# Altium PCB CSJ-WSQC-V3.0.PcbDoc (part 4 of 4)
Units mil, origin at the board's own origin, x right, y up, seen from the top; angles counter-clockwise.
Board outline 5060 x 7131.55 mil, 4 copper layers (Top Layer, InternalPlane1, InternalPlane2, Bottom Layer); 390 components, 277 nets, 1183 pads, 601 vias.
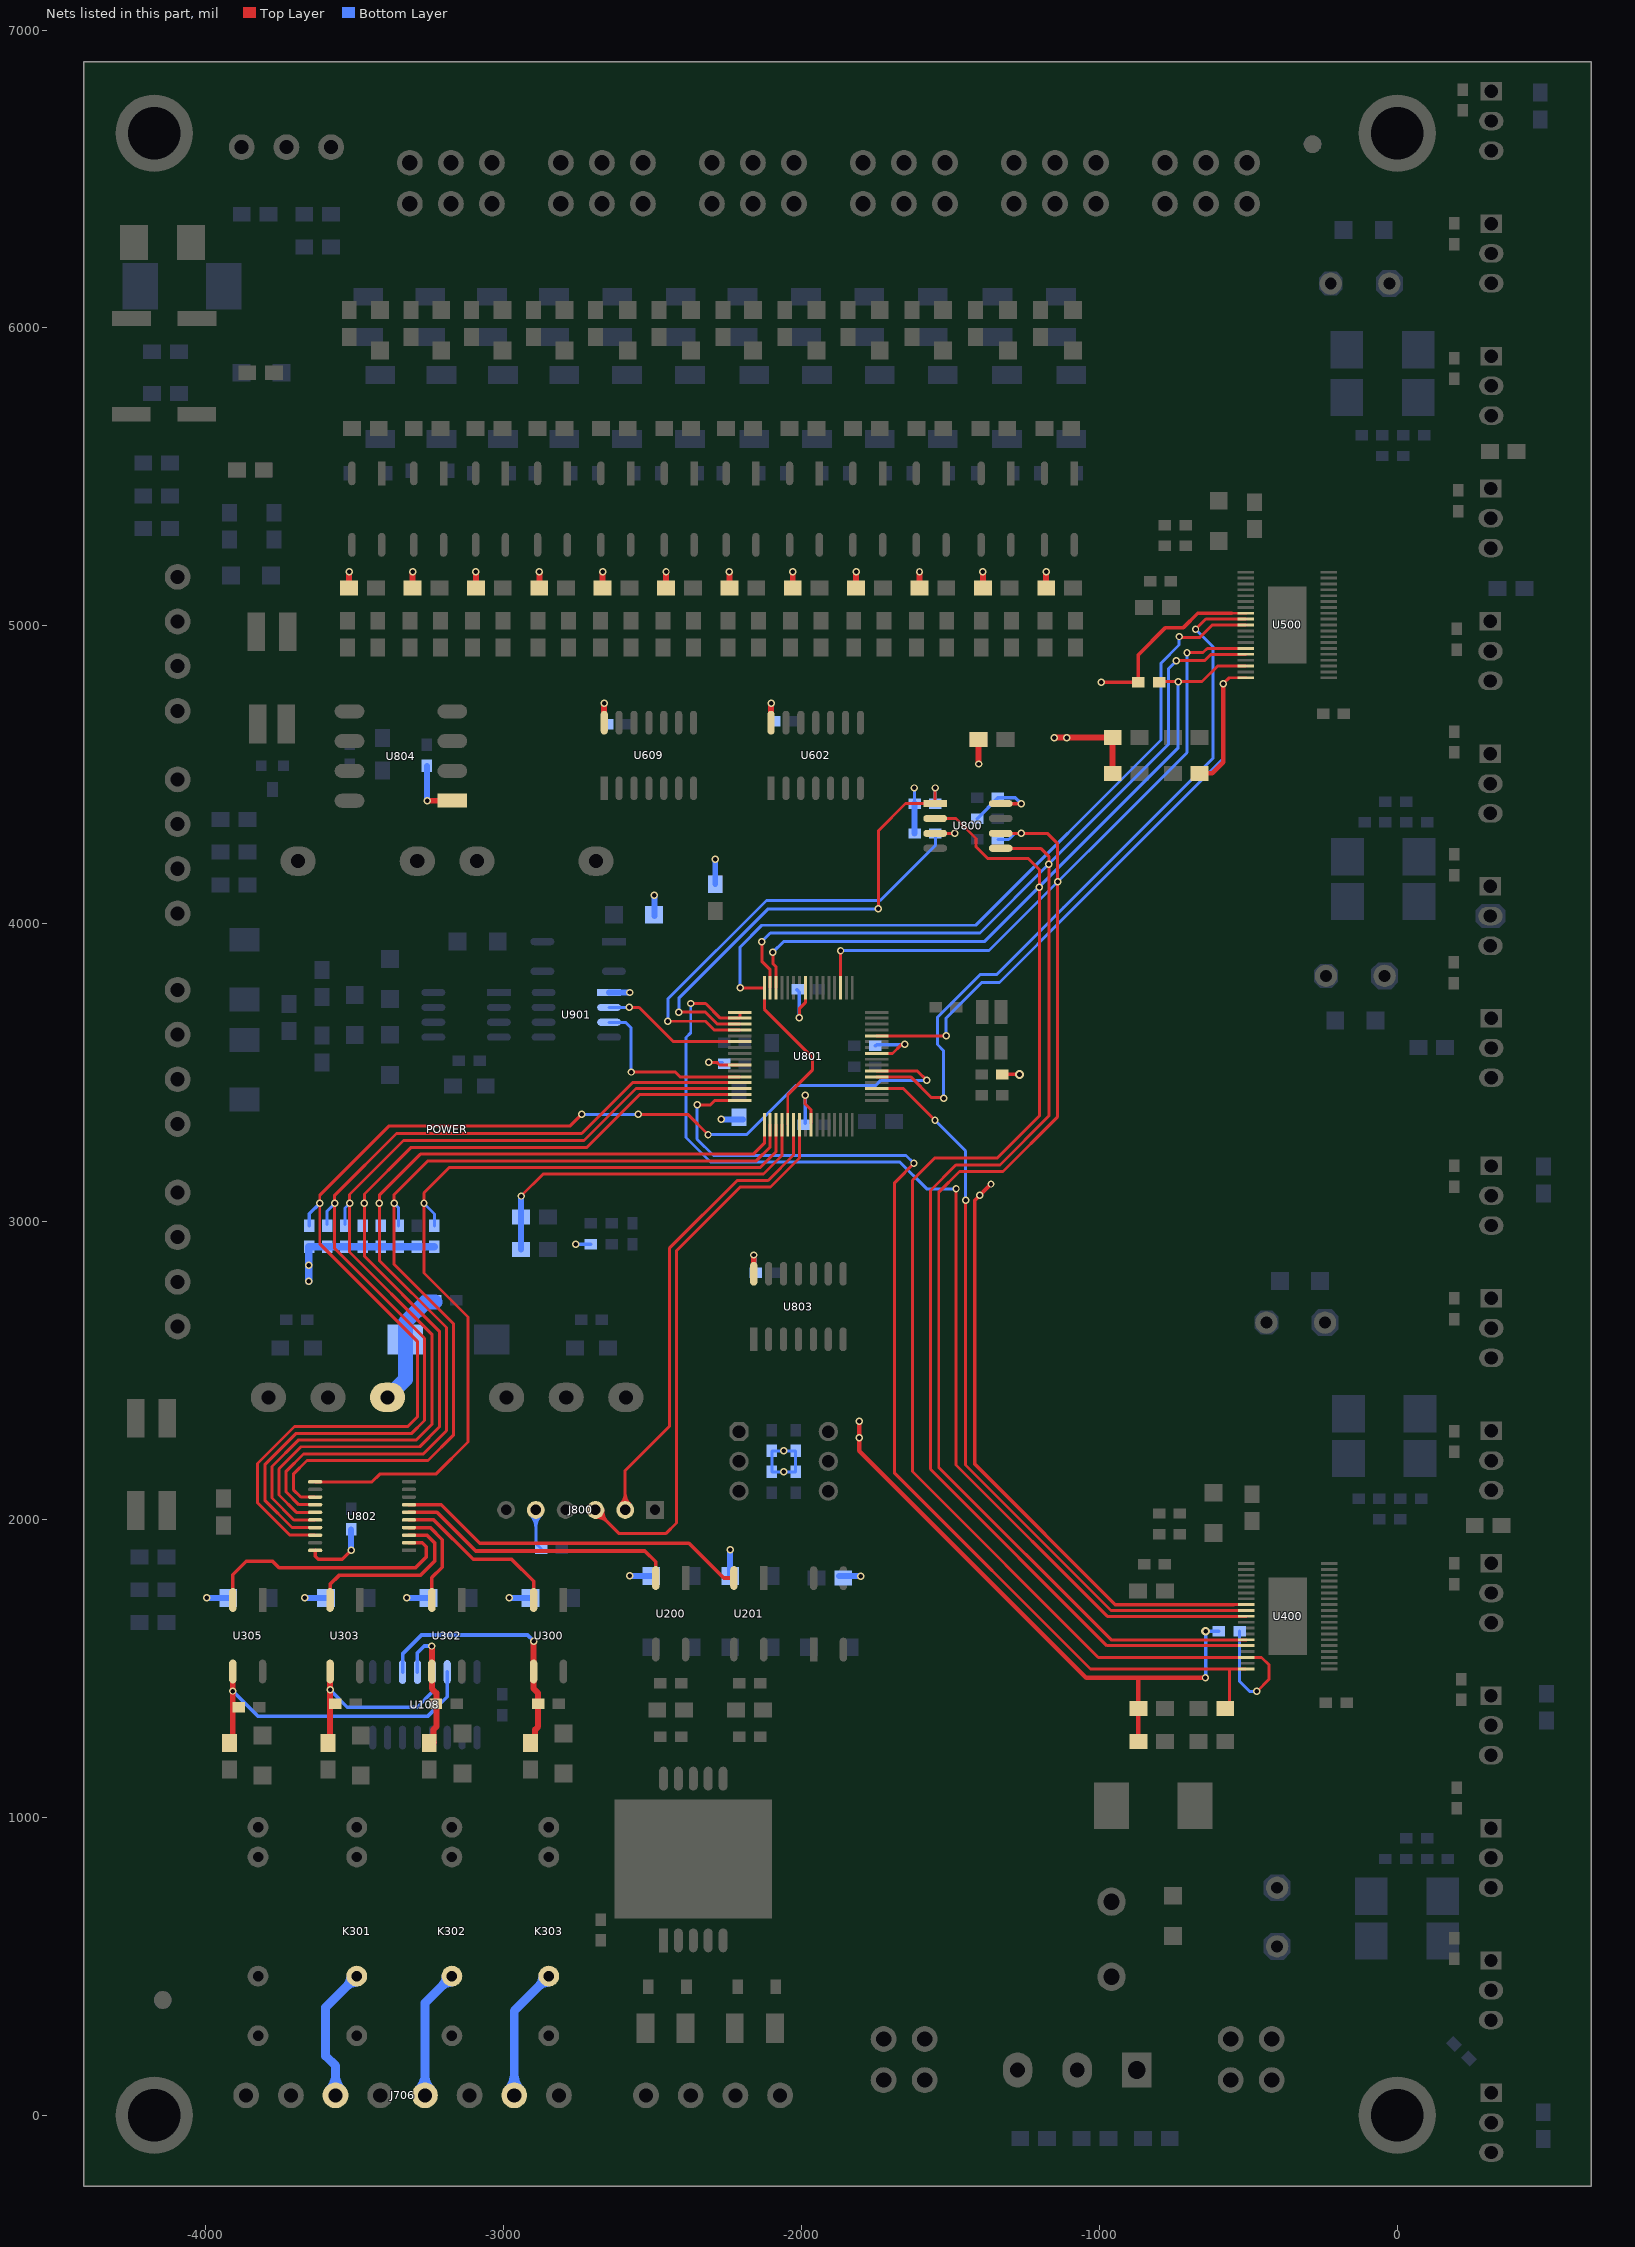
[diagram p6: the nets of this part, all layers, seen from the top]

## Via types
v1: diameter 25, hole 15, Top Layer to Bottom Layer, 303 vias
v2: diameter 25, hole 12, Top Layer to Bottom Layer, 94 vias
v3: diameter 50, hole 25, Top Layer to Bottom Layer, 71 vias
v4: diameter 30, hole 16, Top Layer to Bottom Layer, 71 vias
v5: diameter 12, hole 8, Top Layer to Bottom Layer, 25 vias
v6: diameter 25, hole 12, Top Layer to Bottom Layer, tented both sides, 24 vias
v7: diameter 35, hole 20, Top Layer to Bottom Layer, 7 vias
v8: diameter 20, hole 12, Top Layer to Bottom Layer, 3 vias
v9: diameter 8, hole 5, Top Layer to Bottom Layer, 2 vias
v10: diameter 35, hole 25, Top Layer to Bottom Layer, 1 vias

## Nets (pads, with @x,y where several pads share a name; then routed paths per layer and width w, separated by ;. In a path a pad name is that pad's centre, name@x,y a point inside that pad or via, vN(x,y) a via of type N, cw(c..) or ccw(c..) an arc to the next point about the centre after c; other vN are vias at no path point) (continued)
OUT6: J706.3 K301.2 | length 708.4
  Bottom Layer w30: J706.3@-3584.46,86.75 ccw(c-3632.79,135.07) -3564.45,135.07 ccw(c-3496.11,135.07) J706.3@-3544.43,86.75 ; J706.3@-3564.45,66.73 -3564.45,165.73 -3597.45,198.73 -3597.45,362.4 K301.2@-3493.11,466.73 ; K301.2@-3513.11,466.73 cw(c-3561.4,466.73) -3527.26,432.59 ; -3527.26,432.59 cw(c-3493.11,398.45) -3493.11,446.73 K301.2@-3493.11,466.73 ; -3527.26,432.59 K301.2@-3493.11,466.73
OUT7: J706.5 K302.2 | length 689
  Bottom Layer w30: J706.5@-3284.46,86.75 ccw(c-3332.79,135.07) -3264.45,135.07 ccw(c-3196.11,135.07) J706.5@-3244.43,86.75 ; J706.5@-3264.45,66.73 -3264.45,174 -3264.45,376.07 K302.2@-3173.78,466.73 ; K302.2@-3193.78,466.73 cw(c-3242.07,466.73) -3207.92,432.59 ; -3207.92,432.59 cw(c-3173.78,398.45) -3173.78,446.73 K302.2@-3173.78,466.73 ; -3207.92,432.59 K302.2@-3173.78,466.73
OUT8: J706.7 K303.2 | length 699.5
  Bottom Layer w30: J706.7@-2984.46,86.75 ccw(c-3032.79,135.07) -2964.45,135.07 ccw(c-2896.11,135.07) J706.7@-2944.43,86.75 ; J706.7@-2964.45,66.73 -2964.45,350.73 K303.2@-2848.45,466.73 ; K303.2@-2868.45,466.73 cw(c-2916.73,466.73) -2882.59,432.59 ; -2882.59,432.59 cw(c-2848.45,398.45) -2848.45,446.73 K303.2@-2848.45,466.73 ; -2882.59,432.59 K303.2@-2848.45,466.73
"OUT ALARM_IN1": C205.2 R222.2 U801.20 | length 1215.2
  Top Layer w10: v1(-2941.45,3085.73) -2867.18,3160 -2128,3160 -2066.03,3221.97 U801.20@-2066.03,3325.32
  Bottom Layer w20: R222.2@-2941.45,2905.73 C205.2@-2941.45,3015.73 v1(-2941.45,3085.73)
PGC: J800.2 U801.22 | length 1733.4
  Top Layer w10: J800.2@-2608.69,2050.61 ccw(c-2642.21,2088) -2592,2088 ; J800.2@-2602.01,2043.17 ccw(c-2622.13,2065.6) -2592,2065.6 ccw(c-2561.87,2065.6) J800.2@-2581.99,2043.17 ; J800.2@-2592,2032 -2592,2088 ; -2592,2098 -2592,2088 ; J800.2@-2575.31,2050.61 cw(c-2541.79,2088) -2592,2088 ; U801.22@-2026.66,3325.32 -2026.66,3223.34 -2112,3138 -2216,3138 -2444,2910 -2444,2312 -2592,2164 -2592,2088
PGD: J800.3 U801.23 | length 2039.9
  Top Layer w10: J800.3@-2692,2007 cw(c-2692,1946.65) -2649.32,1989.32 cw(c-2606.64,2032) J800.3@-2667,2032 ; J800.3@-2692,2017 cw(c-2692,1980.79) -2666.39,2006.39 cw(c-2640.79,2032) J800.3@-2677,2032 ; J800.3@-2692,2032 -2612,1952 -2456,1952 -2420,1988 -2420,2902 -2206,3116 -2104,3116 -2006.98,3213.02 U801.23@-2006.98,3325.32
PO5: C300.2 R304.2 U108.3 U300.3 | length 885.9
  Top Layer w20: v1(-2899.45,1591.73) U300.3@-2899.45,1489.53 -2899.45,1431.73 -2884.45,1416.73 C300.2@-2884.45,1381.73 -2884.45,1304.53 -2894.45,1294.53 R304.2@-2894.45,1251.73
  Bottom Layer w12: U108.3@-3339.45,1487.73 -3339.45,1548.55 -3276,1612 -2919.72,1612 v1(-2899.45,1591.73)
PO6: C302.2 R309.2 U108.4 U302.3 | length 457.8
  Top Layer w20: v1(-3241.11,1575.07) U302.3@-3241.11,1489.53 -3241.11,1431.73 -3226.11,1416.73 -3226.11,1304.53 -3236.11,1294.53 -3236.11,1251.73 R309.2@-3234.45,1251.73
  Bottom Layer w12: U108.4@-3289.45,1487.73 -3289.45,1552.55 -3266.93,1575.07 v1(-3241.11,1575.07)
PO7: C303.2 R318.2 U108.5 U303.3 | length 696
  Top Layer w20: R318.2@-3590,1250 -3582.78,1257.22 v1(-3582.78,1428) U303.3@-3582.78,1489.53
  Bottom Layer w12: v1@-3578,1428 -3578,1423.22 -3524.78,1370 -3290,1370 -3239.45,1420.55 U108.5@-3239.45,1487.73
PO8: C305.2 R323.2 U108.6 U305.3 | length 1102.5
  Top Layer w20: R323.2@-3909.45,1260.55 v1(-3909.45,1424) U305.3@-3909.45,1489.53 ; R323.2@-3904.45,1251.73 R323.2@-3904.45,1260.55
  Bottom Layer w12: v1(-3909.45,1424) -3825.45,1340 -3254,1340 -3189.45,1404.55 U108.6@-3189.45,1487.73
PRE485_EN: R819.1 U801.19 U802.11 | length 2885.3
  Top Layer w10: U802.11@-3632.96,2126.31 -3441.69,2126.31 -3416,2152 -3228,2152 -3120,2260 -3120,2680 -3267.45,2827.45 v1(-3267.45,3060.73) -3267.45,3096.55 -3182,3182 -2138,3182 -2085.72,3234.28 U801.19@-2085.72,3325.32
  Bottom Layer w10: v1(-3267.45,3060.73) -3232.45,3025.73 R819.1@-3232.45,2985.73
"PRE 1": R816.1 U801.17 U802.14 | length 3260.2
  Top Layer w10: U802.14@-3632.96,2049.54 -3687.54,2049.54 -3730,2092 -3730,2162 -3672,2220 -3270,2220 -3192,2298 -3192,2644 -3417.45,2869.45 v1(-3417.45,3060.73) ; -3417.45,2965.45 v1(-3417.45,3060.73) ; U801.17@-2125.09,3325.32 -2125.09,3262.91 -2162,3226 -3280,3226 -3417.45,3088.55 v1(-3417.45,3060.73)
  Bottom Layer w10: R816.1@-3417.45,2985.73 v1(-3417.45,3060.73)
"PRE 2": R817.1 U801.18 U802.13 | length 3166
  Top Layer w10: U802.13@-3632.96,2075.13 -3681.13,2075.13 -3706,2100 -3706,2152 -3660,2198 -3254,2198 -3168,2284 -3168,2656 -3367.45,2855.45 -3367.45,3034 ; -3367.45,2969.45 -3367.45,3034 ; U801.18@-2105.4,3325.32 -2105.4,3250.6 -2152,3204 -3254,3204 -3367.45,3090.55 v1(-3367.45,3060.73) -3367.45,3034
  Bottom Layer w10: v1(-3367.45,3060.73) -3352.45,3045.73 R817.1@-3352.45,2985.73
"PRE 5": R815.1 U801.15 U802.15 | length 3216
  Top Layer w10: U802.15@-3632.96,2023.95 -3695.95,2023.95 -3754,2082 -3754,2170 -3680,2244 -3282,2244 -3216,2310 -3216,2632 -3467.45,2883.45 v1(-3467.45,3060.73) -3467.45,3092.55 -3312,3248 -2722,3248 -2543.22,3426.78 -2406,3426.78 ; -2427.22,3426.78 -2406,3426.78 ; U801.15@-2206.86,3426.78 -2406,3426.78
  Bottom Layer w10: R815.1@-3467.45,2980.73 v1(-3467.45,3060.73)
"PRE 6": R814.1 U801.14 U802.16 | length 3347.6
  Top Layer w10: U802.16@-3632.96,1998.36 -3704.36,1998.36 -3778,2072 -3778,2178 -3690,2266 -3294,2266 -3240,2320 -3240,2620 -3517.45,2897.45 v1(-3517.45,3060.73) -3517.45,3090.55 -3336,3272 -2730,3272 -2555.53,3446.47 -2390,3446.47 ; -2439.53,3446.47 -2390,3446.47 ; U801.14@-2206.86,3446.47 -2390,3446.47
  Bottom Layer w10: R814.1@-3532.45,2990.73 -3532.45,3045.73 v1(-3517.45,3060.73)
"PRE 7": R812.1 U801.13 U802.17 | length 3420.7
  Top Layer w10: U802.17@-3632.96,1972.77 -3710.77,1972.77 -3802,2064 -3802,2184 -3698,2288 -3310,2288 -3266,2332 -3266,2608 -3567.45,2909.45 v1(-3567.45,3060.73) -3567.45,3088.55 -3360,3296 -2738,3296 -2567.85,3466.15 -2434,3466.15 ; -2451.85,3466.15 -2434,3466.15 ; U801.13@-2206.86,3466.15 -2434,3466.15
  Bottom Layer w10: R812.1@-3592.45,2990.73 -3592.45,3035.73 v1(-3567.45,3060.73)
"PRE 8": R811.1 U801.38 U802.18 | length 4374.9
  Top Layer w10: U802.18@-3632.96,1947.18 -3717.18,1947.18 -3826,2056 -3826,2188 -3702,2312 -3322,2312 -3290,2344 -3290,2598 -3617.45,2925.45 v1(-3617.45,3060.73) -3617.45,3088.55 -3386,3320 -2778,3320 v1(-2738,3360) ; v1(-2548,3360) -2382,3360 v1(-2314,3292) ; U801.38@-1748.04,3505.52 -1611.52,3505.52 v1(-1580,3474)
  Bottom Layer w10: v1(-2738,3360) v1(-2548,3360) ; v1(-2314,3292) -2184,3292 -2020,3456 -1752,3456 -1734,3474 v1(-1580,3474)
  Bottom Layer w12: R811.1@-3652.45,2985.73 -3652.45,3025.73 v1(-3617.45,3060.73)
"PRE OUT1": U200.2 U802.6 | length 951.4
  Top Layer w12: U802.6@-3318,2023.95 -3223.95,2023.95 -3094,1894 -2526,1894 -2489.45,1857.45 U200.2@-2489.45,1803.53
"PRE OUT2": U201.2 U802.7 | length 1193
  Top Layer w12: U802.7@-3318,2049.54 -3209.54,2049.54 -3080,1920 -2378,1920 -2261.53,1803.53 U201.2@-2226.95,1803.53
"PRE OUT5": U300.2 U802.5 | length 566.5
  Top Layer w12: U802.5@-3318,1998.36 -3234.36,1998.36 -3102,1866 -2973.45,1866 -2899.45,1792 U300.2@-2899.45,1729.53
"PRE OUT6": U302.2 U802.4 | length 345.9
  Top Layer w12: U802.4@-3318,1972.77 -3246.77,1972.77 -3206,1932 -3206,1840 -3241.11,1804.89 U302.2@-3241.11,1729.53
"PRE OUT7": U303.2 U802.3 | length 594
  Top Layer w12: U303.2@-3582.78,1729.53 -3582.78,1782 -3552.78,1812 -3280,1812 -3232,1860 -3232,1922 -3257.18,1947.18 U802.3@-3318,1947.18
"PRE OUT8": U305.2 U802.2 | length 875
  Top Layer w12: U305.2@-3909.45,1729.53 -3909.45,1814.55 -3864,1860 -3776,1860 -3754,1838 -3296,1838 -3260,1874 -3260,1908 -3273.59,1921.59 U802.2@-3318,1921.59
PROTECTION: R807.2 U800.3 U801.4 | length 1610.8
  Top Layer w10: v1(-2448.83,3672.47) -2322.47,3672.47 -2293.32,3643.32 U801.4@-2206.86,3643.32 ; U800.3@-1551.45,4303.17 v1(-1485.06,4303.17)
  Bottom Layer w10: v1@-2448.83,3674.73 -2448.83,3747.17 -2118,4078 -1736,4078 -1550.62,4263.38 R807.2@-1550.62,4302.73 ; R807.2@-1551.45,4302.73 R807.2@-1550.62,4302.73 ; v1(-1485.06,4303.17) -1550.18,4303.17 R807.2@-1550.62,4302.73
RES1: U400.9 U801.35 | length 2583
  Top Layer w10: U801.35@-1748.04,3446.47 -1658.47,3446.47 v1(-1552,3340) ; v1@-1449.45,3074 v1(-1449.45,3072) -1449.45,2182.73 -961.13,1694.42 U400.9@-506.62,1694.42
  Bottom Layer w10: v1(-1552,3340) -1449.45,3237.45 v1@-1449.45,3076
RES2: U500.9 U801.37 | length 2463.5
  Top Layer w10: U801.37@-1748.04,3485.84 -1633.84,3485.84 -1564,3416 v1@-1524,3416 ; v1(-677.45,4988) -643.03,5022.42 U500.9@-508.62,5022.42
  Bottom Layer w10: v1@-1524,3414 -1524,3574 -1544,3594 -1544,3686 -1401.27,3828.73 -1345.45,3828.73 -1118.09,4056.09 ; -1121.09,4053.09 -1118.09,4056.09 ; v1(-677.45,4988) -618,4928.55 -618,4556.18 -1118.09,4056.09
  other v1: -1522,3414
RS485RXD: U801.6 U901.2 | length 486.8
  Top Layer w10: v1(-2579,3719) -2545,3719 -2429.95,3603.95 U801.6@-2206.86,3603.95
  Bottom Layer w10: U901.2@-2646,3719 v1(-2579,3719)
RS485TXD: U801.12 U901.3 | length 601.7
  Top Layer w10: v1(-2572,3502) -2424,3502 -2407.84,3485.84 U801.12@-2206.86,3485.84
  Bottom Layer w10: U901.3@-2646,3669 -2591,3669 -2572,3650 v1(-2572,3502)
SPICLK: R808.1 U400.14 U500.14 U800.6 U801.51 | length 6012.5
  Top Layer w10: U801.51@-1869.18,3784.14 v1(-1869.18,3909.73) ; U800.6@-1331.45,4303.17 v1(-1262.18,4303.17) -1175.17,4303.17 -1140,4268 -1140,4238 v1(-1140,4140) ; v1@-1139.72,4139.72 -1140,4139.43 -1140,3352 -1324,3168 -1470,3168 -1539.45,3098.55 -1539.45,2174.73 -960.71,1595.99 U400.14@-506.62,1595.99 ; v1(-706,4910) -652,4910 -638.01,4923.99 U500.14@-508.62,4923.99
  Bottom Layer w10: v1(-1869.18,3909.73) -1370.45,3909.73 -706,4574.18 v1(-706,4910) ; R808.1@-1340.62,4282.73 -1304.62,4282.73 -1284.18,4303.17 v1(-1262.18,4303.17)
SPISIMO: U400.15 U500.15 U800.5 U801.63 | length 6127.6
  Top Layer w10: v1(-2133.45,3940) -2133.45,3873.45 -2105.4,3845.4 U801.63@-2105.4,3784.14 ; U800.5@-1331.45,4253.17 -1197.17,4253.17 -1170,4226 -1170,4204 v1(-1170,4200) -1170,3354 -1334,3190 -1482,3190 -1567.45,3104.55 -1567.45,2168.73 -975.02,1576.31 U400.15@-506.62,1576.31 ; v1@-742,4882.73 v1@-741.79,4882.73 ; v1@-741.79,4882.94 -647.06,4882.94 -625.69,4904.31 U500.15@-508.62,4904.31
  Bottom Layer w10: v1(-2133.45,3940) -2104.72,3968.73 -1401.27,3968.73 v1(-1170,4200) -768,4602 -768,4856 v1(-742,4882)
SPISOMI: R406.2 R506.2 U400.17 U500.17 U800.2 U801.62 | length 6895.4
  Top Layer w10: v1(-2096.62,3904) -2096.62,3866.62 -2085.72,3855.72 U801.62@-2085.72,3784.14 ; U800.2@-1551.45,4353.17 -1481.17,4353.17 -1414,4286 -1414,4258 -1374,4218 -1238,4218 -1202,4182 v1(-1202,4122) -1202,3790 ; -1202,3812 -1202,3790 ; R506.2@-800,4812.73 v1(-735.45,4812.73) -655.27,4812.73 -603.06,4864.94 U500.17@-508.62,4864.94 ; v1(-471.45,1422.73) -431.45,1462.73 -431.45,1512.73 -455.65,1536.94 U400.17@-506.62,1536.94 -1003.65,1536.94 -1627.45,2160.73 -1627.45,3138.55 -1552,3214 -1342,3214 -1202,3354 -1202,3790
  Bottom Layer w10: v1(-2096.62,3904) -2060.89,3939.73 -1386.27,3939.73 -735.45,4590.55 v1(-735.45,4812.73) ; R406.2@-529.45,1624.73 -529.45,1456.77 -495.41,1422.73 v1(-471.45,1422.73)
SPISTE: R802.2 U800.1 U801.3 | length 1659.5
  Top Layer w10: v1(-2412,3702.73) -2322.73,3702.73 -2283,3663 U801.3@-2206.86,3663 ; v1@-1741.45,4050.55 v1(-1742,4050) -1742,4312.18 -1651.01,4403.17 U800.1@-1551.45,4403.17 v1(-1551.45,4455.56)
  Bottom Layer w10: v1@-2408,3704.73 -2412,3708.73 -2412,3750 -2112,4050 v1(-1742,4050) ; v1(-1551.45,4455.56) -1551.45,4403.56 R802.2@-1550.62,4402.73
STALLN_1: R410.1 U400.19 U801.16 | length 3694.3
  Top Layer w10: v1(-2350,3392) -2306,3392 -2290.91,3407.09 U801.16@-2206.86,3407.09 ; v1@-1618,3200 -1687.45,3130.55 -1687.45,2154.73 -1030.28,1497.57 -563.45,1497.57 ; R410.1@-589.45,1364.73 -563.45,1390.73 -563.45,1497.57 ; U400.19@-509.45,1497.57 -563.45,1497.57
  Bottom Layer w10: v1@-2350.62,3392 -2350.62,3276.62 -2296,3222 -1649.17,3222 v1(-1622.59,3195.41)
STALLN_2: R510.1 U500.19 U801.44 | length 2297.9
  Top Layer w10: U801.44@-1748.04,3623.63 v1(-1514.37,3623.63) v1@-1514,3624 ; v1(-584,4806) -564.43,4825.57 U500.19@-508.62,4825.57
  Top Layer w15: R510.1@-675.45,4504.73 R510.1@-663.45,4504.73 -621.27,4504.73 -584,4542 v1(-584,4806)
  Bottom Layer w10: v1@-1514.37,3622.73 -1514.37,3683.63 -1395.27,3802.73 -1335.45,3802.73 -1080.09,4058.09 ; -1084.09,4054.09 -1080.09,4058.09 ; v1(-584,4806) -584,4554.18 -1080.09,4058.09
STEP_1: U400.10 U801.1 U801.2 | length 3752.2
  Top Layer w10: v1(-2372,3732) -2322,3732 -2272.69,3682.69 U801.2@-2206.86,3682.69 U801.1@-2206.86,3702.37 ; v1(-1481.45,3110) -1481.45,2182.73 -973.45,1674.73 U400.10@-506.62,1674.73
  Bottom Layer w10: v1(-2372,3732) -2372,3634 -2388,3618 -2388,3282 -2306,3200 -1670,3200 -1580,3110 v1(-1481.45,3110)
STEP_2: U500.10 U801.21 U801.64 | length 3091.3
  Top Layer w10: v1(-2206,3784.73) U801.64@-2125.68,3784.73 ; U801.64@-2125.09,3784.14 -2125.09,3713.09 -1964,3552 -1964,3508 -2046.35,3425.65 U801.21@-2046.35,3325.32 ; v1@-732,4960 -664,4960 -621.27,5002.73 U500.10@-508.62,5002.73
  Bottom Layer w10: v1(-2206,3784.73) -2206,3922 -2133.27,3994.73 -1415.27,3994.73 -793.45,4616.55 -793.45,4874.55 -732.5,4935.5 v1@-732.5,4964
  other v1: -732,4964
VCC: C110.1 C111.1 C612.1 C613.1 C800.2 C802.1 C807.1 C809.1 C810.1 C811.1 C812.1 C817.1 C818.1 D102.1 D400.1 D401.1 D500.1 D501.1 J800.5 L100.1 L800.1 POWER.8 R201.2 R205.2 R220.1 R301.2 R306.2 R315.2 R320.2 R406.1 R506.1 R600.2 R601.2 R610.2 R611.2 R620.2 R621.2 R630.2 R631.2 R640.2 R641.2 R650.2 R651.2 R800.2 R801.1 R802.1 R803.2 R804.1 R805.1 R806.2 R807.1 R810.2 R811.2 R812.2 R814.2 R815.2 R816.2 R817.2 R818.2 R819.2 R904.2 U400.8 U500.8 U602.14 U609.14 U800.8 U801.10 U801.25 U801.41 U801.57 U802.20 U803.14 U804.1 U901.1 | length 10160.7
  Top Layer w10: v1(-2312,3534.73) -2284.62,3534.73 -2275.09,3525.21 U801.10@-2206.86,3525.21 ; v1(-2007.45,3684.73) -2007.45,3714.73 -1987.29,3734.89 U801.57@-1987.29,3779.14 ; v1(-1987.76,3424.73) -1987.76,3394.73 -1967.61,3374.58 U801.25@-1967.61,3330.32 ; U801.41@-1723.04,3564.58 -1694.78,3564.58 -1665.53,3593.82 v1@-1648.53,3593.82 ; L800.1@-1325.45,3493.73 L800.1@-1325.18,3493.73 ; -556,5042.1 U500.8@-508.62,5042.1 ; -550,1714.1 U400.8@-506.62,1714.1
  Top Layer w12: U802.20@-3632.05,1895.09 U802.20@-3632.96,1896 -3632.96,1876.96 -3622,1866 -3542,1866 v1@-3512.91,1895.09 ; v1(-1364,3126) -1418,3072 -1418,2185.28 -946.82,1714.1 -550,1714.1 ; U800.8@-1331.45,4403.17 v1(-1263.06,4403.17) ; L800.1@-1325.18,3494 v4(-1268,3494) ; v1(-994,4810) R506.1@-870,4810 -870,4902 -778,4994 -718,4994 -669.9,5042.1 -556,5042.1
  Top Layer w15: v1(-1806,2330) -1806,2230 -1044,1468 -869.45,1468 ; D401.1@-869.45,1254.73 D400.1@-869.45,1364.73 -869.45,1468 ; v1@-640,1468 -869.45,1468
  Top Layer w20: R651.2@-3518.62,5126.73 v1(-3518.62,5181.73) ; R641.2@-3305.89,5126.73 v1(-3305.89,5181.73) ; v1(-3256.73,4412.73) U804.1@-3172.45,4412.73 ; R631.2@-3093.17,5126.73 v1(-3093.17,5181.73) ; R621.2@-2880.44,5126.73 v1(-2880.44,5181.73) ; R611.2@-2667.71,5126.73 v1(-2667.71,5181.73) ; U609.14@-2662.45,4674.73 v1(-2662.45,4739.73) ; R601.2@-2454.99,5126.73 v1(-2454.99,5181.73) ; R650.2@-2242.26,5126.73 v1(-2242.26,5181.73) ; U803.14@-2160.45,2824.73 v1(-2160.45,2887.73) ; U602.14@-2102.45,4674.73 v1(-2102.45,4739.73) ; R640.2@-2029.53,5126.73 v1(-2029.53,5181.73) ; R630.2@-1816.8,5126.73 v1(-1816.8,5181.73) ; R620.2@-1604.08,5126.73 v1(-1604.08,5181.73) ; v1(-1405.38,4536) D102.1@-1405.38,4618.44 ; R610.2@-1391.35,5126.73 v1(-1391.35,5181.73) ; R600.2@-1178.62,5126.73 v1(-1178.62,5181.73) ; v1(-1152,4624.73) D501.1@-955.45,4624.73 D500.1@-955.45,4504.73
  Bottom Layer w10: J800.5@-2909.68,2014.32 cw(c-2952.36,1971.65) -2892,1971.65 cw(c-2831.64,1971.65) J800.5@-2874.32,2014.32 ; J800.5@-2902.61,2021.39 cw(c-2928.21,1995.79) -2892,1995.79 cw(c-2855.79,1995.79) J800.5@-2881.39,2021.39 ; J800.5@-2892,2032 -2892,1919.72 C800.2@-2874.55,1902.27 ; v1(-2312,3534.73) C812.1@-2264.73,3534.73 ; C809.1@-2017.45,3779.73 C809.1@-2014.95,3777.23 ; R802.1@-1621.45,4403.56 v1(-1621.45,4455.56) ; R803.2@-2100,2160 R804.1@-2020,2160 R801.1@-2020,2230 R800.2@-2100,2230 R803.2@-2100,2160
  Bottom Layer w12: v1(-2758.45,2923.73) R806.2@-2707.45,2923.73 ; C809.1@-2014.95,3777.23 -2007.45,3769.73 v1(-2007.45,3684.73) ; C811.1@-1987.76,3329.42 v1(-1987.76,3424.73) ; C810.1@-1752.45,3589.73 -1751.62,3589.73 -1747.62,3593.73 -1648.45,3593.73 v1@-1648.53,3593.82 ; R805.1@-1410.62,4352.73 C802.1@-1340.62,4422.73 -1282.62,4422.73 v1(-1263.06,4403.17) ; v1@-643.45,1468 v4(-643.45,1624.73) R406.1@-599.45,1624.73
  Bottom Layer w20: v1(-3996.73,1736.73) R320.2@-3924.45,1736.73 ; v1(-3668.4,1736.73) R315.2@-3596.11,1736.73 ; v1(-3512,1896) C818.1@-3512,1966 ; v1(-3325.07,1736.73) R306.2@-3252.78,1736.73 ; v1(-3256.73,4412.73) C807.1@-3256.73,4528.73 ; v1(-2981.73,1736.73) R301.2@-2909.45,1736.73 ; C613.1@-2662.45,4679.73 v1(-2662.45,4739.73) ; U901.1@-2646,3769 v1(-2577,3769) ; v1(-2576.73,1810.73) R201.2@-2504.45,1810.73 ; R904.2@-2494,4026 v1(-2494,4095) ; R810.2@-2289.73,4132.55 v1@-2289.73,4215.37 ; v1(-2269.27,3342.73) L100.1@-2196.62,3342.73 ; R205.2@-2239.45,1810.73 v1(-2239.45,1898) ; C817.1@-2160.45,2834.73 v1(-2160.45,2887.73) ; C612.1@-2102.45,4679.73 v1(-2102.45,4739.73) ; R220.1@-1874.45,1810.73 v1@-1802,1810.73 ; R807.1@-1620.62,4302.73 R802.1@-1620.62,4402.73
  Bottom Layer w25: v1(-3654,2800) -3654,2915.73 R812.2@-3592.45,2915.73 R814.2@-3532.45,2915.73 R815.2@-3472.45,2915.73 R816.2@-3412.45,2915.73 R817.2@-3352.45,2915.73 R818.2@-3292.45,2915.73 R819.2@-3232.45,2915.73
  Bottom Layer w50: POWER.8@-3390,2410 -3330,2470 -3330,2610 -3330,2662 -3262,2730 C110.1@-3230,2730
  other v1: -644,1468 -1802,1810 -2060,2160 -2060,2230 -1806,2274 -3654,2854 -1401.88,3088.12 -1653.45,3594.73 -2290,4216 -1110,4624.73
pads on no net: J800.1 POWER.1 POWER.4 Q400.0 Q401.0 Q402.0 Q403.0 Q404.0 Q405.0 Q406.0 Q407.0 Q500.0 Q501.0 Q502.0 Q503.0 Q504.0 Q505.0 Q506.0 Q507.0 U108.1 U108.2 U108.7 U108.10 U108.15 U108.16 U203.2 U203.3 U203.8 U203.9 U400.12 U400.13 U500.12 U500.13 U802.8 U803.5 U803.6 U803.8 U803.9 Y800.1
copper on no net:
  other v10: -10259.45,10714.53

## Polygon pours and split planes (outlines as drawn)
GND on Top Layer "Top Layer-No Net 1" (solid, pour order 1002): -1620,3792 -1260,3792 -1260,3374.65 -1297.16,3337.49 -1455.44,3337.49 -1466,3348.05 -1466,3352 -1466,3622 -1510,3666 -1620,3666 -1620,3792
+48V on Top Layer "Top Layer-No Net 1" (solid, pour order 1001): -1394,628 -1394,468 -1392,466 -1324,398 -1208,398 -1084,398 -1082,400 -1082,626 -1392,626 -1396,630
+48V on Top Layer "Top Layer-No Net 1" (solid, pour order 1000): -858,1132 -1392.72,1132 -1393.45,1132.73 -1393.45,604.55 -1394,604 -858,604 -856,602 -856,1132.18 -855.45,1132.73
AOUT1 on Top Layer "Bottom Layer-No Net" (solid, remove dead copper, pour order 1000): 19 vertices, not listed, extent 252,2604 594.55,3024
no net on Top Layer "Bottom Layer-No Net" (solid, pour order 1001): -384.45,6716.73 -384.45,6516.73 -184.45,6516.73 -184.45,6716.73 -384.45,6716.73
no net on Top Layer "Bottom Layer-No Net" (solid, pour order 1000): -4244.45,486.73 -4244.45,286.73 -4044.45,286.73 -4044.45,486.73 -4244.45,486.73
GND on Top Layer "Bottom Layer-No Net" (solid, remove dead copper, pour order 1001): -205.45,4572.73 -149.45,4572.73 -149.45,4606.73 -239.45,4696.73 -297.45,4754.73 -297.45,4866.73 -297.45,5194.73 -243.45,5248.73 -133.45,5358.73 -133.45,5486.73 -405.45,5486.73 -405.45,5280.73 -441.45,5244.73 -441.45,4572.73 -205.45,4572.73
AOUT3 on Top Layer "Bottom Layer-No Net" (solid, remove dead copper, pour order 1005): 506.55,3474.73 418.55,3386.73 418.55,3286.73 622.55,3286.73 624.55,3284.73 624.55,3474.73 506.55,3474.73
GND on Top Layer "Bottom Layer-No Net" (solid, remove dead copper, pour order 1002): 22 vertices, not listed, extent -495.45,1212.73 -199.45,2044.73
GND on Top Layer "Bottom Layer-No Net" (solid, remove dead copper, pour order 1005): -1186,360 -1186,-110 -971.88,-110 -970,-112 -970,280 -1045.13,360 -1186,360
+48VIN on Top Layer "Bottom Layer-No Net" (solid, remove dead copper, pour order 1006): -932,-108 -932,328.91 -990,387.85 -1028,426.46 -1028,507.74 -1028,521.97 -692,521.97 -690,524 -690,-108 -932,-108
GND on Top Layer "Bottom Layer-No Net" (solid, remove dead copper, pour order 1000): -756.55,5371.27 -756.55,5231.5 -754.55,5229.38 -872.55,5229.38 -874.55,5227.27 -874.55,5369.15 -876.55,5371.27 -756.55,5371.27
GND on Top Layer "Bottom Layer-No Net" (solid, remove dead copper, pour order 1001): -776.55,2053.27 -776.55,1913.5 -774.55,1911.38 -892.55,1911.38 -894.55,1909.27 -894.55,2051.15 -896.55,2053.27 -776.55,2053.27
GND on Top Layer "Bottom Layer-No Net" (solid, remove dead copper, pour order 1002): -406,5464 -406,5626 -136,5626 -134,5626 -134,5462 -136,5464 -406,5464
GND on Top Layer "Bottom Layer-No Net" (solid, remove dead copper, pour order 1004): 17 vertices, not listed, extent -500,2012 -200,2700
GND on Top Layer "Bottom Layer-No Net" (solid, remove dead copper, pour order 1005): -134,6028 -134,6152 -180,6198 -302,6198 -342,6158 -480,6020 -480,5968 -192,5968 -134,6026
GND on Top Layer "Bottom Layer-No Net" (solid, remove dead copper, pour order 1007): -648,3580 -152,3580 -152,4376 -646,4376 -646,3582 -648,3580
GND on Top Layer "Bottom Layer-No Net" (solid, remove dead copper, pour order 1000): -18,376 -282,376 -282,956 -210,956 -134,880 -18,764 -18,714 -18,374.83 -18.83,374
GND on Top Layer "Bottom Layer-No Net" (solid, remove dead copper, pour order 1001): -452,6048 -484,6016 -484,5970 -484,5556 -482,5554 -134,5554 -134,6048 -452,6048
AOUT2 on Top Layer "Bottom Layer-No Net" (solid, remove dead copper, pour order 1002): 268,1608 582,1608 618,1644 618,2192 584,2226 567.27,2242.73 262.55,2242.73 262.55,2156.55 262,2156 385.28,2156 452,2089.28 452,1742 406,1696 268,1696 268,1608
AOUT3 on Top Layer "Bottom Layer-No Net" (solid, remove dead copper, pour order 1003): 21 vertices, not listed, extent 252,3288 636,6664.73
BOUT2 on Top Layer "Bottom Layer-No Net" (solid, remove dead copper, pour order 1004): 18 vertices, not listed, extent 248,-186 608,458.73
+48V on Bottom Layer "Top Layer-No Net 1" (solid, pour order 1005): -856,950 -856,604 -1128,604 -1128,676 -856,950
+48V on Bottom Layer "Top Layer-No Net 1" (solid, pour order 1004): -1123.45,1132.73 -855.45,1132.73 -855.45,930.55 -1082,704 -1082,436 -1362,436 -1396,470 -1396,860 -1336,920 -1123.45,1132.55 -1123.45,1132.73
24VGND on Bottom Layer "Top Layer-No Net 1" (solid, pour order 1003): -3714,5780 -3714,5720 -3632,5638 -3610,5616 -3560,5616 -3560,5780 -3714,5780
NetQ402_3 on Bottom Layer "Bottom Layer-No Net" (solid, remove dead copper, pour order 1005): 20 vertices, not listed, extent 12,1980 396,2580
BOUT3 on Bottom Layer "Bottom Layer-No Net" (solid, remove dead copper, pour order 1004): 390,4510 390,4434 194,4434 124,4504 110,4518 110,4802 162,4854 286,4854 392,4854 392,4668 266,4668 234,4636 234,4536 260,4510 390,4510
AOUT3 on Bottom Layer "Bottom Layer-No Net" (solid, remove dead copper, pour order 1003): 254,6630 552,6630 584,6598 622.55,6559.45 622.55,6284.73 553.82,6216 250,6216 250,6286 380,6286 412,6318 412,6392 348,6456 256,6456 254,6458 254,6630
BOUT1 on Bottom Layer "Bottom Layer-No Net" (solid, remove dead copper, pour order 1002): 234,1244 558,1244 588,1214 612,1190 612,876 566,830 564,828 250,828 250,902 376,902 420,946 420,1030 378,1072 234,1072 234,1244
AOUT1 on Bottom Layer "Bottom Layer-No Net" (solid, remove dead copper, pour order 1001): 17 vertices, not listed, extent 256,2606 594.55,3026
GND on Bottom Layer "Bottom Layer-No Net" (solid, remove dead copper, pour order 1005): -500,2450 -500,2808 -452,2856 -342,2856 -342,2610 -280,2548 -102,2548 -102,2448 -498,2448 -500,2450
GND on Bottom Layer "Bottom Layer-No Net" (solid, remove dead copper, pour order 1003): -455.45,4118.73 -648,3926.18 -648,3908 -648,3580 -166,3580 -152,3594 -152,4060 -154,4062 -210.73,4118.73 -455.45,4118.73
GND on Bottom Layer "Bottom Layer-No Net" (solid, remove dead copper, pour order 1002): -500,2032 -500,2464 -396,2464 -396,2136 -500,2032
GND on Bottom Layer "Bottom Layer-No Net" (solid, remove dead copper, pour order 1001): -100,2114 -100,1206 -96,1202 -498,1202 -500,1200 -500,2038 -422,2116 -420,2114 -100,2114
GND on Bottom Layer "Bottom Layer-No Net" (solid, remove dead copper, pour order 1000): -95.45,5576.73 -95.45,4556.55 -96,4556 -456,4556 -494,4556 -494,5576 -490,5580 -94,5580 -94,5576
no net on Bottom Layer "Bottom Layer-No Net" (solid, pour order 1004): -384.45,6716.73 -384.45,6516.73 -184.45,6516.73 -184.45,6716.73 -384.45,6716.73
no net on Bottom Layer "Bottom Layer-No Net" (solid, pour order 1003): -4244.45,486.73 -4244.45,286.73 -4044.45,286.73 -4044.45,486.73 -4244.45,486.73
AOUT4 on Bottom Layer "Bottom Layer-No Net" (solid, remove dead copper, pour order 1008): 622.55,5282.73 622.55,3286.73 492.55,3286.73 490.55,3284.73 490.55,5280.73 492.55,5282.73 622.55,5282.73
AOUT4 on Bottom Layer "Bottom Layer-No Net" (solid, remove dead copper, pour order 1016): 622.55,3286.73 290.55,3286.73 288.55,3288.73 288.55,3310.73 396.55,3418.73 508.55,3530.73 622.55,3530.73 622.55,3286.73
BOUT2 on Bottom Layer "Bottom Layer-No Net" (solid, remove dead copper, pour order 1017): 260.55,-83.27 260.55,-199.27 424,-199.27 424,-83.27 260.55,-83.27
AOUT2 on Bottom Layer "Bottom Layer-No Net" (solid, remove dead copper, pour order 1007): 19 vertices, not listed, extent 228.55,1530.73 596.55,2240.73
GND on Bottom Layer "Bottom Layer-No Net" (solid, remove dead copper, pour order 1010): -17.45,884.73 -17.45,246.73 -175.45,246.73 -175.45,782.73 -65.45,892.73 -17.45,892.73 -17.45,884.73
GND on Bottom Layer "Bottom Layer-No Net" (solid, remove dead copper, pour order 1011): -101.45,2040.73 -101.45,2462.73 -99.45,2464.73 -421.45,2464.73 -423.45,2466.73 -423.45,2102.73 -235.45,2102.73 -175.45,2042.73 -173.45,2040.73 -101.45,2040.73
GND on Bottom Layer "Bottom Layer-No Net" (solid, remove dead copper, pour order 1012): -85.45,4376.73 -197.45,4376.73 -253.45,4320.73 -455.45,4118.73 -455.45,3974.73 -455.45,3926.73 -83.45,3926.73 -83.45,4376.73 -87.45,4376.73
GND on Bottom Layer "Bottom Layer-No Net" (solid, remove dead copper, pour order 1013): -95.45,5576.73 -95.45,6000.73 -483.45,6000.73 -485.45,6002.73 -485.45,5574.73 -97.45,5574.73 -95.45,5576.73
GND on Bottom Layer "Bottom Layer-No Net" (solid, remove dead copper, pour order 1005): -96,5958 -96,6026 -134,6064 -134,6398 -306,6398 -444,6260 -485.45,6218.55 -485.45,5976.55 -485.45,5949.45 -474,5938 -116,5938 -96,5958
NetQ406_3 on Bottom Layer "Bottom Layer-No Net" (solid, remove dead copper, pour order 1007): 20 vertices, not listed, extent 92,254 406,804
NetQ506_3 on Bottom Layer "Bottom Layer-No Net" (solid, remove dead copper, pour order 1008): 19 vertices, not listed, extent 4,3784 392,4408
NetQ502_3 on Bottom Layer "Bottom Layer-No Net" (solid, remove dead copper, pour order 1009): 21 vertices, not listed, extent 16.55,5628 402,6188
AOUT4 on Bottom Layer "Bottom Layer-No Net" (solid, remove dead copper, pour order 1010): 23 vertices, not listed, extent 246.55,5174 622,5850
+48VIN on Bottom Layer "Bottom Layer-No Net" (solid, remove dead copper, pour order 1000): -1028,524 -846,524 -846,407.37 -750,309.15 -690,247.77 -690,4.28 -690,-8 -932,-8 -932,329.62 -1028,427.83 -1028,524
GND on Bottom Layer "Bottom Layer-No Net" (solid, remove dead copper, pour order 1001): -1186,360 -1043.89,360 -970,282 -970,92 -970,-8 -1186,-8 -1186,360
GND on InternalPlane1 (split plane): 123 vertices, not listed, extent -4174.38,-218.17 630.46,6873.18
24VGND on InternalPlane1 (split plane): 70 vertices, not listed, extent -4389.35,-218.17 -418.52,6873.18
485G1 on InternalPlane1 (split plane): 49 vertices, not listed, extent -4174.38,1919.07 -2754.08,4073.92
5VGND on InternalPlane1 (split plane): 36 vertices, not listed, extent -4174.38,3926.08 -3355.07,5614.93
24VGND on InternalPlane1 (split plane): 81 vertices, not listed, extent -4294.44,6532.33 -4052.02,6774.76
GND on InternalPlane1 (split plane): 81 vertices, not listed, extent -121.21,6532.33 121.21,6774.76
GND on InternalPlane1 (split plane): 81 vertices, not listed, extent -121.21,-121.21 121.21,121.21
24VGND on InternalPlane1 (split plane): 81 vertices, not listed, extent -4294.44,-121.21 -4052.02,121.21
+24V on InternalPlane2 (split plane): 66 vertices, not listed, extent -4389.35,-218.17 -418.52,6873.18
VCC on InternalPlane2 (split plane): 101 vertices, not listed, extent -4174.38,1633.07 -951.07,5370.93
+48V on InternalPlane2 (split plane): 64 vertices, not listed, extent -1950.38,-218.17 630.46,6873.18
+48V on InternalPlane2 (split plane): 630.46,-218.17 -672.93,-218.17 -672.93,594 -673.22,596.94 -674.07,599.77 -675.47,602.37 -677.34,604.66 -679.63,606.53 -682.23,607.93 -685.06,608.78 -688,609.07 -1042.93,609.07 -1042.93,2441.76 -163.02,3321.66 630.46,3321.66
485P1 on InternalPlane2 (split plane): 40 vertices, not listed, extent -4174.38,1919.07 -2754.08,4073.92
+5V on InternalPlane2 (split plane): 34 vertices, not listed, extent -4174.38,3926.08 -3355.07,5612.93
+48V on InternalPlane2 (split plane): 18 vertices, not listed, extent -1434.93,-218.17 -703.07,578.93
+24V on InternalPlane2 (split plane): 81 vertices, not listed, extent -4294.44,6532.33 -4052.02,6774.76
+48V on InternalPlane2 (split plane): 81 vertices, not listed, extent -121.21,6532.33 121.21,6774.76
+48V on InternalPlane2 (split plane): 81 vertices, not listed, extent -121.21,-121.21 121.21,121.21
+24V on InternalPlane2 (split plane): 81 vertices, not listed, extent -4294.44,-121.21 -4052.02,121.21

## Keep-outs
Keep-Out Layer:
  lines w20: -4409.45,-238.27 -4409.45,6893.28 550.55,6893.28 650.55,6893.28 650.55,-238.27 -4409.45,-238.27

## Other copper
Top Layer:
  rectangle net +24V: -2698.45,656.73 -2028.45,1061.73
Bottom Layer:
  rectangle net +24V: -3900,5642 -3754,5760
  rectangle net +24V: -2698.45,656.73 -2028.45,1061.73
InternalPlane1 (plane layer: these items are gaps in the copper):
  circle w50: c0,6653.54 r146.22
  circle w50: c-4173.23,6653.54 r146.22
  circle w50: c-4173.23,0 r146.22
  circle w50: c0,0 r146.22
  lines w30: -4189.45,1902 -4187.45,1904 -3976,1904 -3976,2488 ; -3406,4090 -3406,4250 -3404,4250 -3340,4314 -3340,4834 -3340.55,4834.55 -3599.45,4834.55 -3599.45,5386 ; -1965.45,-239.27 -1965.45,1314.55 -1762,1518 ; -1764,1516 -1758,1522 -1758,1698 -2652,1698 -2652,1618 -4189.45,1618 -4189.45,5630 -3949.45,5630 -3599.45,5630 -3599.45,5386 ; -403.45,6893.28 -403.45,6346.55 -938,5812 -938,5386 -3599.45,5386
  lines w32: -4189.45,2490 -4187.45,2488 ; -4189.45,3910 -4088,3910 -3908,4090 -2814,4090 -2738,4014 -2738,3572 -2982,3328 -3630,3328 -3798,3160 -3798,2666 -3976,2488
InternalPlane2 (plane layer: these items are gaps in the copper):
  circle w50: c-4173.23,0 r146.22
  circle w50: c-4173.23,6653.54 r146.22
  circle w50: c0,6653.54 r146.22
  circle w50: c0,0 r146.22
  lines w30: -4189.45,1904 -3976,1904 -3976,2488 ; -3599.45,5390 -3599.45,4834.55 -3340,4834.55 -3340,4314 -3406,4248 -3406,4090 ; -1965.45,-238.27 -1965.45,1314.55 -1764,1516 ; -1450,-240 -1450,378 -1058,378 -1058,520 -1058,600 ; -936,5394 -936,4702 -1058,4580 -1058,3348 -1757.45,2648.55 -1757.45,1522 -1757.45,1698 -2652,1698 -2652,1618 -4189.45,1618 -4189.45,5628 -3949.45,5628 -3599.45,5628 -3599.45,5386 -936,5386 -936,5814 -403.45,6346.55 -403.45,6893.28 ; -688,-236.27 -688,594 -1058,594 -1058,2448 -169.27,3336.73 650.55,3336.73
  lines w32: -4189.45,3910 -4088,3910 -3908,4090 -2814,4090 -2738,4014 -2738,3572 -2982,3328 -3630,3328 -3798,3160 -3798,2666 -3976,2488

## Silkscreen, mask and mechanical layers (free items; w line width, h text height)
Top Overlay:
  rectangle: -4413.41,3878 -3988.61,3930.01
  text "+24V" at -3959.45,6426.73 h40
  text "GND" at -3779.45,6426.73 h40
  text "PE" at -3604.45,6426.73 h40
  text "+24V" at -3394.45,6291.73 h40
  text "0V" at -3209.45,6291.73 h40
  text "IN11" at -3084.45,6291.73 h40
  text "+24V" at -2887.45,6291.73 h40
  text "0V" at -2702.45,6291.73 h40
  text "IN9" at -2577.45,6291.73 h40
  text "+24V" at -2380.45,6291.73 h40
  text "0V" at -2195.45,6291.73 h40
  text "IN7" at -2070.45,6291.73 h40
  text "+24V" at -1873.45,6291.73 h40
  text "0V" at -1688.45,6291.73 h40
  text "IN5" at -1563.45,6291.73 h40
  text "+24V" at -1366.45,6291.73 h40
  text "0V" at -1181.45,6291.73 h40
  text "IN3" at -1056.45,6291.73 h40
  text "+24V" at -859.45,6291.73 h40
  text "0V" at -674.45,6291.73 h40
  text "IN1" at -549.45,6291.73 h40
  text "IN12" at -3084.45,6226.73 h40
  text "IN10" at -2577.45,6226.73 h40
  text "IN8" at -2070.45,6226.73 h40
  text "IN6" at -1563.45,6226.73 h40
  text "IN4" at -1056.45,6226.73 h40
  text "IN2" at -549.45,6226.73 h40
  text "+24V" at -3886,6010 h40
  text "+5V" at -3908,5418 h40
  text "CANL" at -4008,5222 h35 r270
  text "CANH" at -4008,5074 h35 r270
  text "GND" at -4008,4916 h35 r270
  text "EGND" at -4008,4774 h35 r270
  text "VCC" at -1248,4676 h40
  text "FAULT_2" at -612,4614 h25
  text "STALL_2" at -614,4500 h25
  text "STATUS" at -2212,4082 h40
  text "485B" at -4026,3828 h28 r270
  text "485A" at -4026,3676 h28 r270
  text "GND" at -4024,3512 h28 r270
  text "EGND" at -4024,3374 h28 r270
  text "5V-485" at -4038,1862 h40
  text "STALL_1" at -902,1438 h25
  text "FAULT_1" at -896,1174 h25
  text "motor2" at -1798,330 h50
  text "motor1" at -622,330 h50
  text "GND" at -1146,324 h50
  text "+48V" at -890,322 h50
  text "CSJ-WSQC-V3.0" at -4250,318 h120 r90
  text "PE" at -1314,278 h50
  text "OUT1" at -2599.45,151.73 h40
  text "0V" at -2409.45,151.73 h40
  text "OUT2" at -2299.45,151.73 h40
  text "0V" at -2099.45,151.73 h40
  text "OUT1" at -3930,148 h40
  text "OUT3" at -3338,146 h40
  text "OUT2" at -3636,144 h40
  text "OUT4" at -3044,144 h40

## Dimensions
-4409.45,6893.28 to -4409.45,-238.27 on Mechanical 4
-4409.45,6893.28 to 650.55,6893.28 on Mechanical 4
-4173.23,0 to -4173.23,6653.54 on Mechanical 4
-4173.23,6653.54 to 0,6653.54 on Mechanical 4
